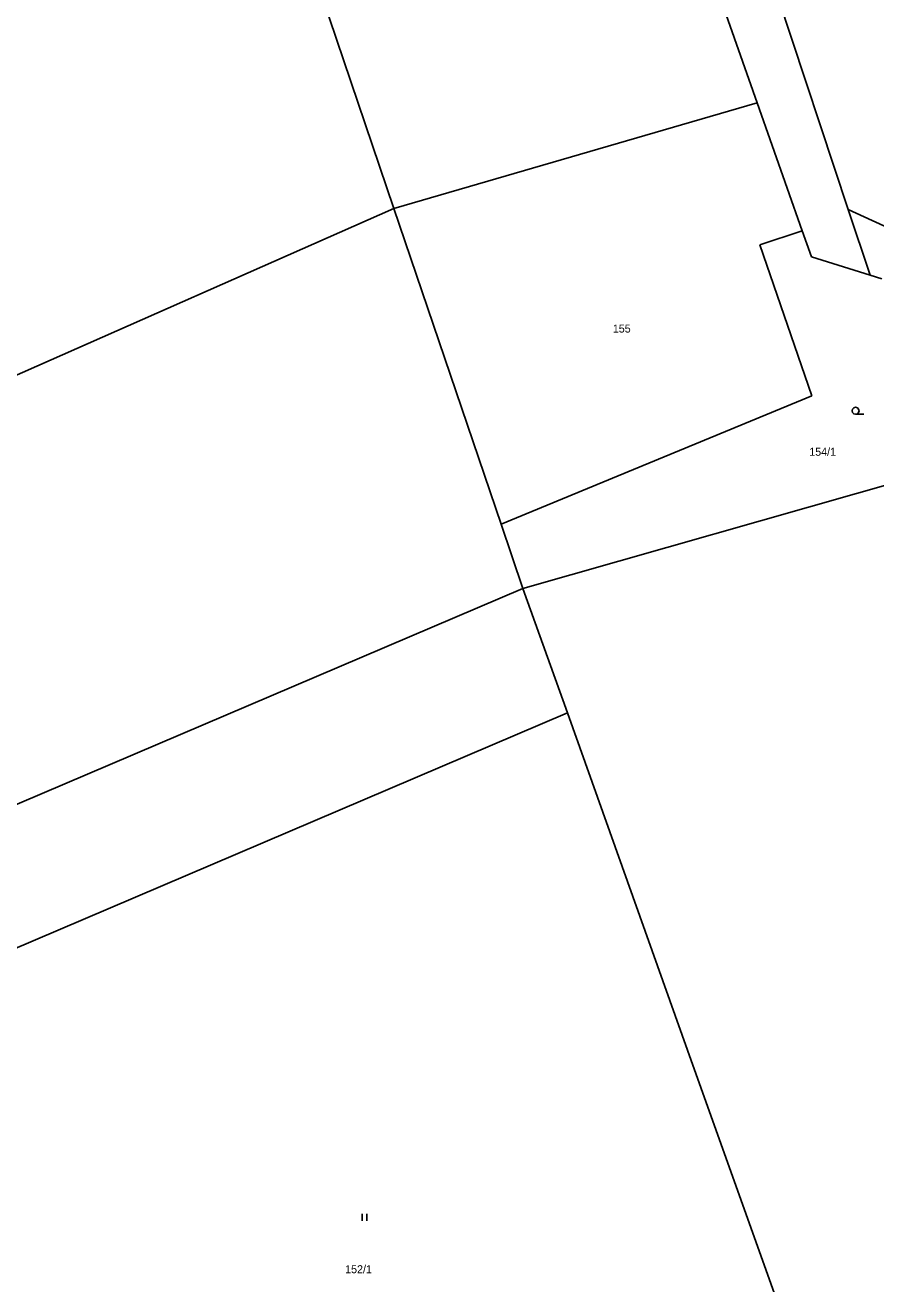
# Model space of a CAD drawing. Extents: x -871430 to -870620, y -1010094 to -1009649.
# Drawn here: x -870823.3 to -870778.1, y -1009951.2 to -1009884.4 of the extents above; entities that cross this region are included whole.
import ezdxf

# ---------------------------------------------------------------- set-up
doc = ezdxf.new("R2010")
doc.units = 0
for name, color, linetype in [('Vrstva 1', 7, 'Continuous'), ('Vrstva 2', 7, 'Continuous'), ('Vrstva 3', 7, 'Continuous')]:
    doc.layers.add(name, color=color, linetype=linetype)

msp = doc.modelspace()

# ---------------------------------------------------------------- linework, layer by layer
at = {"layer": 'Vrstva 1'}
for p, q in [((-870784.39, -1009888.53), (-870797.46, -1009851.56)), ((-870803.69, -1009894.13), (-870815.36, -1009859.75)), ((-870789.8, -1009863.3), (-870779.56, -1009894.18)), ((-870784.39, -1009888.53), (-870803.69, -1009894.13)), ((-870782, -1009895.31), (-870784.39, -1009888.53)), ((-870835.36, -1009908.1), (-870803.69, -1009894.13)), ((-870798, -1009910.89), (-870803.69, -1009894.13)), ((-870779.56, -1009894.18), (-870778.4, -1009897.67)), ((-870779.56, -1009894.18), (-870776.82, -1009895.44)), ((-870784.25, -1009896.06), (-870782, -1009895.31)), ((-870781.51, -1009896.7), (-870782, -1009895.31)), ((-870781.5, -1009904.08), (-870784.25, -1009896.06)), ((-870778.4, -1009897.67), (-870781.51, -1009896.7)), ((-870777.78, -1009897.86), (-870778.4, -1009897.67)), ((-870798, -1009910.89), (-870781.5, -1009904.08)), ((-870796.84, -1009914.3), (-870774.58, -1009907.96)), ((-870796.84, -1009914.3), (-870798, -1009910.89)), ((-870850.67, -1009937.26), (-870796.84, -1009914.3)), ((-870794.48, -1009920.9), (-870796.84, -1009914.3)), ((-870788.09, -1009938.81), (-870794.48, -1009920.9)), ((-870780.02, -1009961.43), (-870788.09, -1009938.81))]:
    msp.add_line(p, q, dxfattribs=at)
msp.add_lwpolyline([(-870830.66, -1009955.85), (-870836.43, -1009946.41), (-870833.62, -1009937.6), (-870794.48, -1009920.9)], dxfattribs=at)
at = {"layer": 'Vrstva 3'}
for p, q in [((-870805.385, -1009947.505), (-870805.385, -1009947.88)), ((-870805.135, -1009947.88), (-870805.135, -1009947.505))]:
    msp.add_line(p, q, dxfattribs=at)
msp.add_lwpolyline([(-870779.17, -1009905.06), (-870779.265, -1009905.035), (-870779.332, -1009904.965), (-870779.358, -1009904.872), (-870779.332, -1009904.78), (-870779.265, -1009904.71), (-870779.17, -1009904.685), (-870779.075, -1009904.71), (-870779.008, -1009904.78), (-870778.982, -1009904.872), (-870779.008, -1009904.965), (-870779.075, -1009905.035), (-870779.17, -1009905.06), (-870778.732, -1009905.06)], dxfattribs=at)

# ---------------------------------------------------------------- texts
at = {"layer": 'Vrstva 2'}
for s, p in [('155', (-870792.065, -1009900.72)), ('154/1', (-870781.632, -1009907.26)), ('152/1', (-870806.283, -1009950.66))]:
    msp.add_text(s, height=0.425, dxfattribs=at).set_placement(p)

doc.saveas('drawing.dxf')
